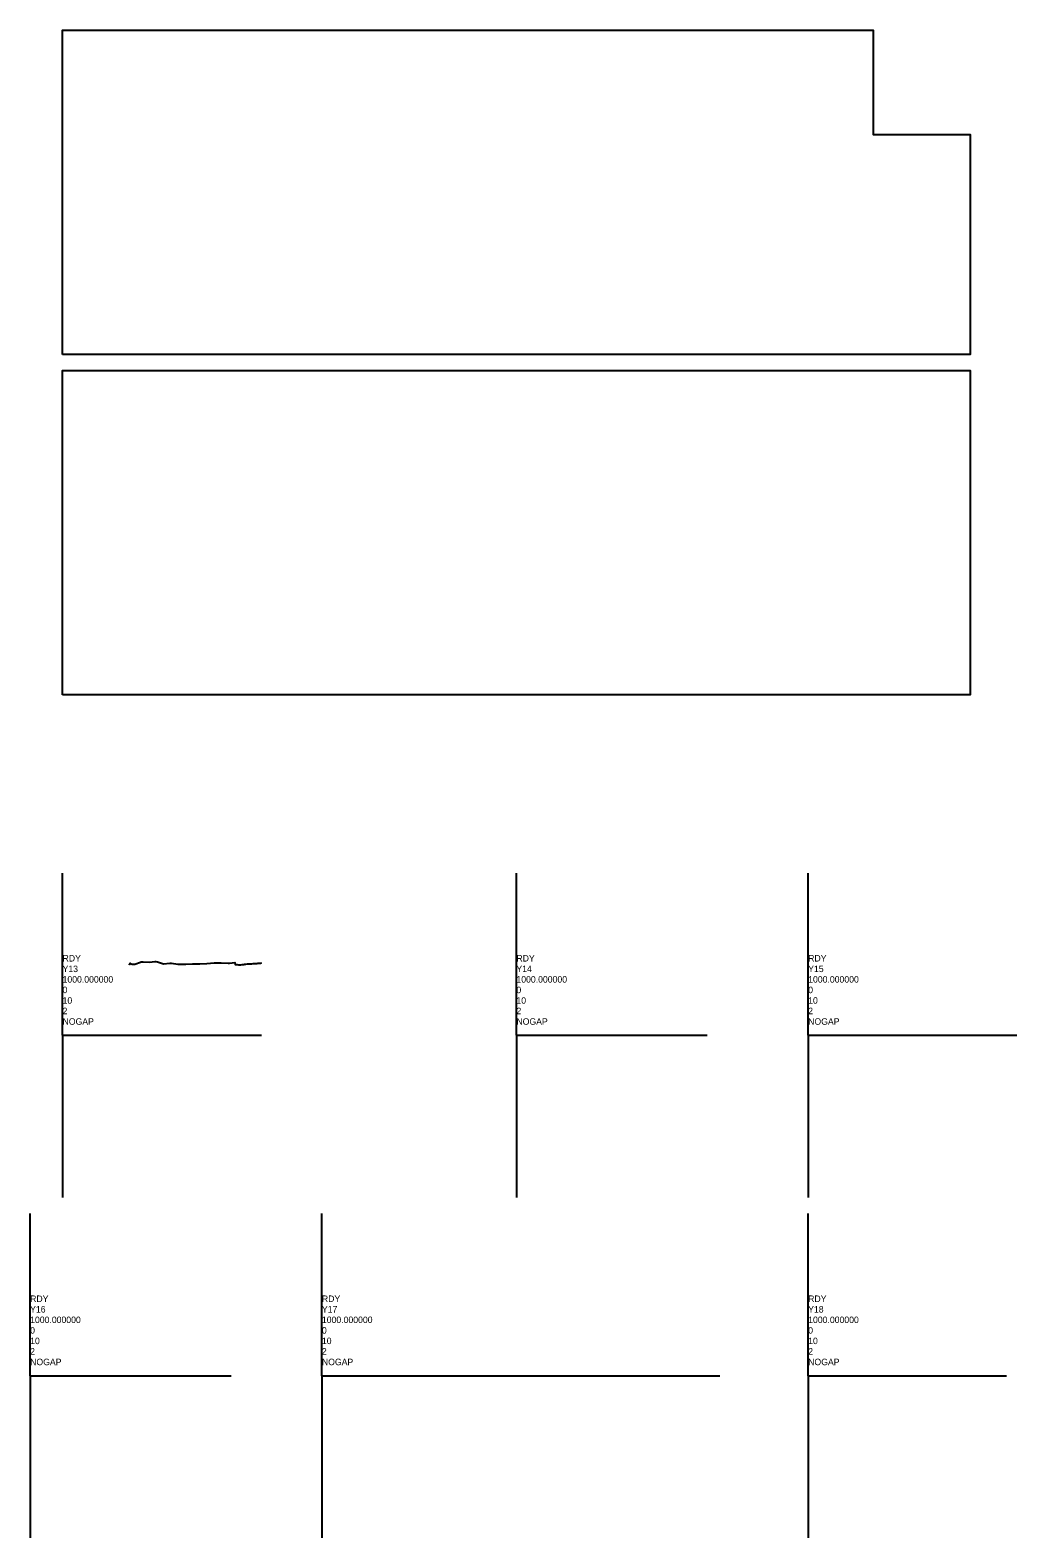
# Model space of a CAD drawing. Extents: x 2319808 to 2329388, y 152694 to 160631.
# Drawn here: x 2320171 to 2321693, y 154975 to 157300 of the extents above; entities that cross this region are included whole.
import ezdxf

# ---------------------------------------------------------------- set-up
doc = ezdxf.new("R2010")
doc.units = 0
for name, color, linetype in [('Exist Profile Cell', 7, 'Continuous'), ('Scratch_Level_0', 7, 'Continuous'), ('Scratch_Level_1', 7, 'Continuous'), ('Scratch_Level_3', 7, 'Continuous')]:
    doc.layers.add(name, color=color, linetype=linetype)

msp = doc.modelspace()

# ---------------------------------------------------------------- linework, layer by layer
at = {"layer": 'Exist Profile Cell'}
for p, q in [((2320221, 155749.7), (2320221, 155999.7)), ((2320921, 155749.7), (2320921, 155999.7)), ((2321371, 155749.7), (2321371, 155999.7)), ((2320221, 155749.7), (2320528, 155749.7)), ((2320221, 155749.7), (2320221, 155499.7)), ((2320921, 155749.7), (2321212.3, 155749.7)), ((2320921, 155749.7), (2320921, 155499.7)), ((2321371, 155749.7), (2321692.8, 155749.7)), ((2321371, 155749.7), (2321371, 155499.7)), ((2320171, 155224.7), (2320171, 155474.7)), ((2320621, 155224.7), (2320621, 155474.7)), ((2321371, 155224.7), (2321371, 155474.7)), ((2320171, 155224.7), (2320481.1, 155224.7)), ((2320171, 155224.7), (2320171, 154974.7)), ((2320621, 155224.7), (2321234.6, 155224.7)), ((2320621, 155224.7), (2320621, 154974.7)), ((2321371, 155224.7), (2321676.7, 155224.7)), ((2321371, 155224.7), (2321371, 154974.7))]:
    msp.add_line(p, q, dxfattribs=at)
at = {"layer": 'Scratch_Level_0'}
for points in [[(2320221, 156799.7), (2320221, 157299.7), (2321471, 157299.7), (2321471, 157138.6), (2321621, 157138.6), (2321621, 156799.7)], [(2320221, 156274.7), (2320221, 156774.7), (2321621, 156774.7), (2321621, 156274.7)]]:
    msp.add_lwpolyline(points, close=True, dxfattribs=at)
at = {"layer": 'Scratch_Level_1'}
msp.add_lwpolyline([(2320324, 155858.1), (2320324.4, 155859.1), (2320325.1, 155859.2), (2320325.1, 155861.1), (2320326, 155860.2), (2320328.4, 155859.1), (2320332.2, 155859.4), (2320341.2, 155862.5), (2320342.4, 155862.9), (2320343.2, 155862.9), (2320345.3, 155862.9), (2320354.4, 155862.2), (2320363.9, 155863.5), (2320365.1, 155863.5), (2320367.2, 155863.1), (2320376.7, 155859.9), (2320386.6, 155860.7), (2320387.8, 155860.8), (2320389, 155860.7), (2320399, 155859.1), (2320409.3, 155859.3), (2320409.9, 155859.2), (2320410.9, 155859.3), (2320421.3, 155859.9), (2320432, 155859.8), (2320432.4, 155859.8), (2320432.8, 155859.8), (2320443.5, 155860.5), (2320454.7, 155861.6), (2320465.8, 155861.5), (2320476.5, 155860.8), (2320477.4, 155860.8), (2320478.7, 155860.9), (2320486.8, 155861.8), (2320487.3, 155859), (2320488.4, 155858.9), (2320489.4, 155858.8), (2320490.3, 155858.8), (2320492.1, 155858.4), (2320494, 155858.5), (2320494.6, 155858.5), (2320495.3, 155858.5), (2320496.2, 155858.5), (2320497.8, 155858.7), (2320499.6, 155859), (2320500.5, 155859), (2320501.5, 155859.2), (2320503.5, 155859.3), (2320506.1, 155859.6), (2320509.2, 155859.8), (2320510.8, 155860), (2320511.6, 155860), (2320512.7, 155860.1), (2320514.8, 155860.2), (2320516.4, 155860.2), (2320517.2, 155860.3), (2320518.3, 155860.4), (2320520.2, 155860.5), (2320520.5, 155860.6), (2320522, 155860.8), (2320522.8, 155860.9), (2320523.9, 155861), (2320525.8, 155861), (2320526.2, 155861), (2320527.6, 155861.2), (2320528, 155861.2)], dxfattribs=at)
at = {"layer": 'Scratch_Level_3'}
for p, q in [((2320221, 155749.7), (2320515.3, 155749.7)), ((2320921, 155749.7), (2321215.3, 155749.7)), ((2321371, 155749.7), (2321665.3, 155749.7)), ((2320171, 155224.7), (2320465.3, 155224.7)), ((2320621, 155224.7), (2320915.3, 155224.7)), ((2321371, 155224.7), (2321665.3, 155224.7))]:
    msp.add_line(p, q, dxfattribs=at)

# ---------------------------------------------------------------- texts
at = {"layer": 'Exist Profile Cell'}
for s, p in [('RDY', (2320221, 155863.4)), ('RDY', (2320921, 155863.4)), ('RDY', (2321371, 155863.4)), ('Y13', (2320221, 155847.1)), ('Y14', (2320921, 155847.1)), ('Y15', (2321371, 155847.1)), ('0', (2320221, 155814.6)), ('1000.000000', (2320221, 155830.9)), ('0', (2320921, 155814.6)), ('1000.000000', (2320921, 155830.9)), ('0', (2321371, 155814.6)), ('1000.000000', (2321371, 155830.9)), ('10', (2320221, 155798.4)), ('10', (2320921, 155798.4)), ('10', (2321371, 155798.4)), ('2', (2320221, 155782.2)), ('NOGAP', (2320221, 155765.9)), ('2', (2320921, 155782.2)), ('NOGAP', (2320921, 155765.9)), ('2', (2321371, 155782.2)), ('NOGAP', (2321371, 155765.9)), ('RDY', (2320171, 155338.4)), ('RDY', (2320621, 155338.4)), ('RDY', (2321371, 155338.4)), ('Y16', (2320171, 155322.1)), ('1000.000000', (2320171, 155305.9)), ('Y17', (2320621, 155322.1)), ('1000.000000', (2320621, 155305.9)), ('Y18', (2321371, 155322.1)), ('1000.000000', (2321371, 155305.9)), ('0', (2320171, 155289.6)), ('0', (2320621, 155289.6)), ('0', (2321371, 155289.6)), ('2', (2320171, 155257.2)), ('10', (2320171, 155273.4)), ('2', (2320621, 155257.2)), ('10', (2320621, 155273.4)), ('2', (2321371, 155257.2)), ('10', (2321371, 155273.4)), ('NOGAP', (2320171, 155240.9)), ('NOGAP', (2320621, 155240.9)), ('NOGAP', (2321371, 155240.9))]:
    msp.add_text(s, height=10, dxfattribs=at).set_placement(p)

doc.saveas('drawing.dxf')
